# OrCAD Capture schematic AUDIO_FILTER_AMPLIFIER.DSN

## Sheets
1 MAIN_AMP_PG1: size A
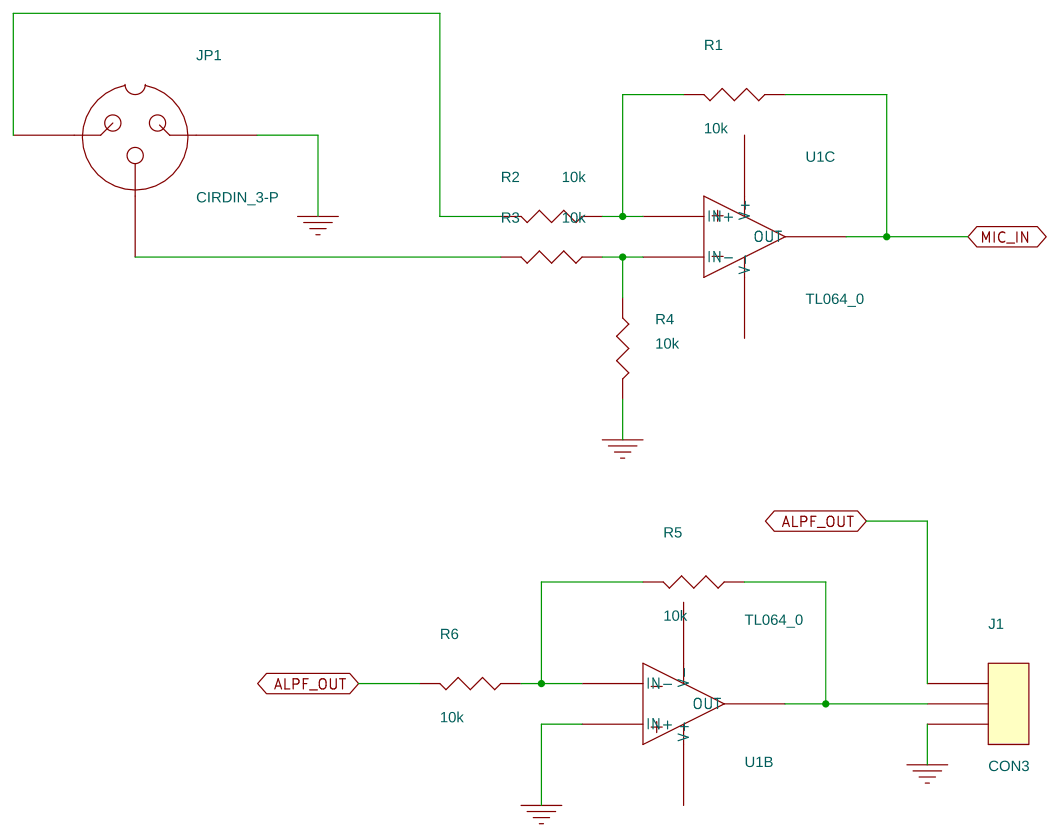
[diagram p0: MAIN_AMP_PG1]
2 MAIN_AMP_PG2: size A
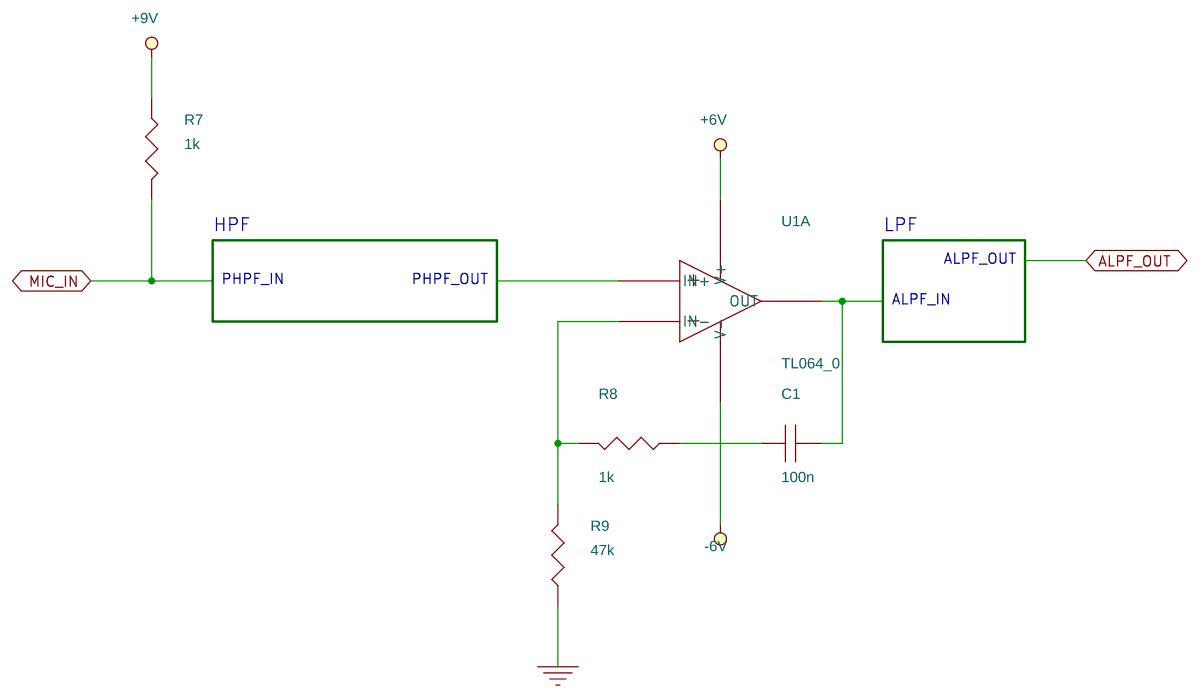
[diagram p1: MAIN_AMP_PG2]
3 AUDIO_HPF_PG1: size A; block HPF
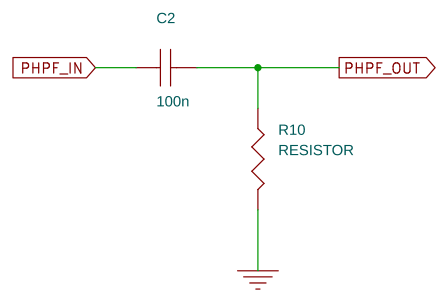
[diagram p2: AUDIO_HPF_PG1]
4 AUDIO_LPF_PG1: size A; block LPF
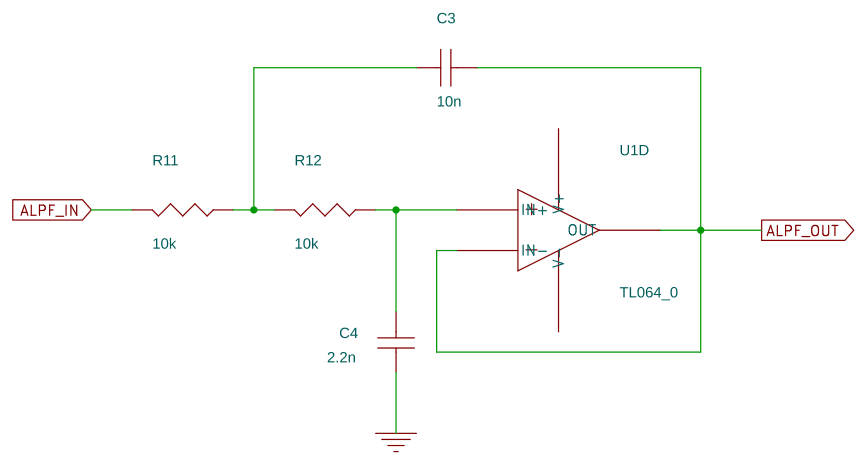
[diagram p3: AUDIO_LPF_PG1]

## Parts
sheet AUDIO_HPF_PG1
C2  100n
R10  RESISTOR
sheet AUDIO_LPF_PG1
C3  10n
C4  2.2n
R11  10k
R12  10k
sheet MAIN_AMP_PG1
J1  CON3
JP1  CIRDIN_3-P
R1  10k
R2  10k
R3  10k
R4  10k
R5  10k
R6  10k
sheet MAIN_AMP_PG2
C1  100n
R7  1k
R8  1k
R9  47k
U1  TL064_0  (sections A,B,C,D)

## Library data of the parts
C1-C4 = CAP_NP
R1-R12 = RESISTOR
J1 = CON3
JP1 = CIRDIN_3-P
U1 = TL064_0

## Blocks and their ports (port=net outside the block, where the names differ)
HPF = schematic AUDIO_HPF, on sheet MAIN_AMP_PG2: PHPF_IN=MIC_IN, PHPF_OUT=N00173
LPF = schematic AUDIO_LPF, on sheet MAIN_AMP_PG2: ALPF_IN=N00334, ALPF_OUT

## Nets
+6V: U1.4(V+)
+9V: R7.1
-6V: U1.11(V-)
GND: C4.1 J1.3 JP1.3 R4.2 R9.1 R10.2 U1.5(IN+)
ALPF_OUT: C3.2 J1.1 R6.2 U1.13(IN-) U1.14(OUT)
MIC_IN: C2.1 R1.1 R7.2 U1.8(OUT)
LPF/N01218: C3.1 R11.2 R12.2
LPF/N01308: C4.2 R12.1 U1.12(IN+)
N00173: C2.2 R10.1 U1.3(IN+)
N00221: R8.2 R9.2 U1.2(IN-)
N00325: C1.1 R8.1
N00334: C1.2 R11.1 U1.1(OUT)
N01240: R5.2 R6.1 U1.6(IN-)
N01283: J1.2 R5.1 U1.7(OUT)
N01591: R1.2 R2.1 U1.10(IN+)
N01615: JP1.1 R2.2
N01688: R3.1 R4.1 U1.9(IN-)
N01750: JP1.2 R3.2
